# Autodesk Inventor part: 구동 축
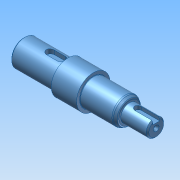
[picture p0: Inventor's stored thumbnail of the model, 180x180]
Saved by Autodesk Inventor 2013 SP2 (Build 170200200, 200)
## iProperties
Created: 2025-09
Part Number: 구동 축
Material: Generic
Document SubType Name: Modeling
Designer: a
Density: 1 g/cm^3
Author: a
변환 표준: STEP AP214IS
전처리기: Build: 200, Release: 2013 SP2 Update 6 - Date: Thu 07/17/2014
전송 단위: 밀리미터
불확실성: 0.01
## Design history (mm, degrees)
node "구동 축1"
node "솔리드1"
node "기준1"
